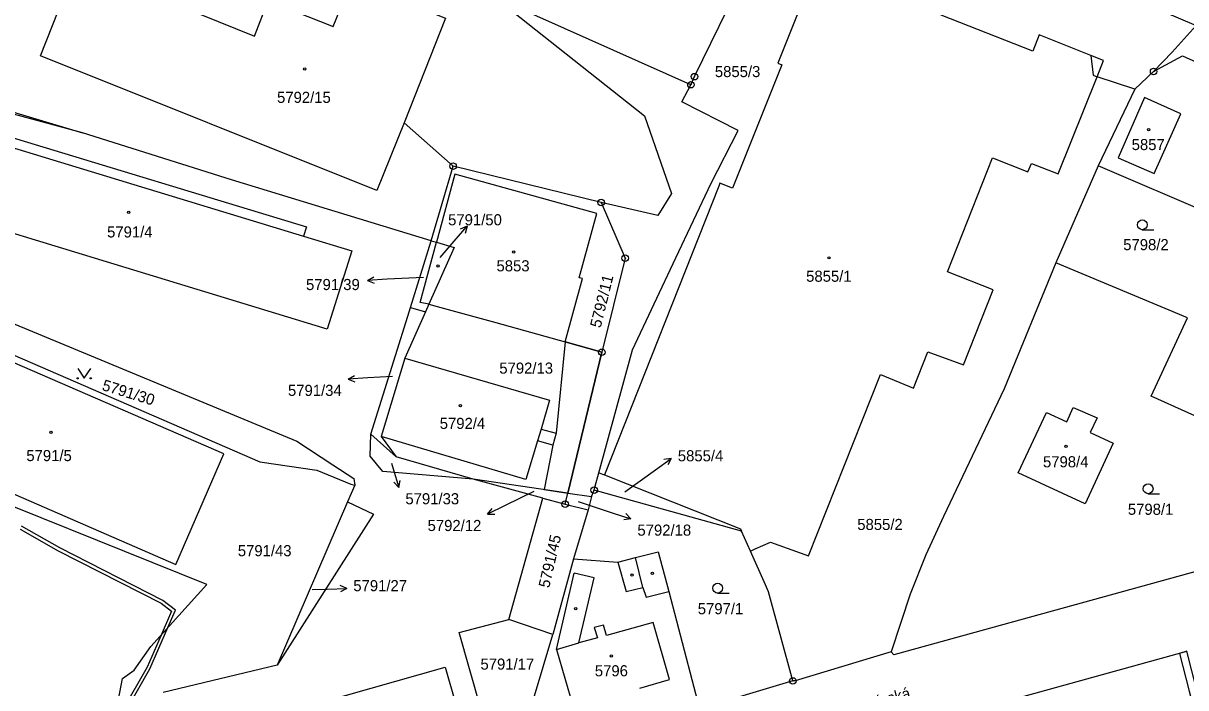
# Model space of a CAD drawing. Extents: x -644096 to -634268, y -1141430 to -1133463.
# Drawn here: x -640057.5 to -639879.7, y -1138714.8 to -1138613.2 of the extents above; entities that cross this region are included whole.
import ezdxf

# ---------------------------------------------------------------- set-up
doc = ezdxf.new("R2010")
doc.units = 0
for name, color, linetype in [('_CIVIL_CONSTRUCTION', 7, 'Continuous'), ('B_Hranice _3D', 7, 'Continuous'), ('M_Svah_Nasyp', 7, 'Continuous'), ('M_Svah_Zarez', 7, 'Continuous'), ('svrsek_osa_sjezdy', 7, 'Continuous'), ('svrsek_osa_VRT', 7, 'Continuous'), ('svrsek_popisy_VRT', 7, 'Continuous'), ('terminal_VRT', 7, 'Continuous')]:
    doc.layers.add(name, color=color, linetype=linetype)

msp = doc.modelspace()

# ---------------------------------------------------------------- linework, layer by layer
at = {"layer": '_CIVIL_CONSTRUCTION'}
for centre, radius in [((-639954.84, -1138621.41), 0.5), ((-639884.63, -1138620.63), 0.5), ((-639884.63, -1138620.63), 0.0303), ((-639955.38, -1138622.64), 0.5), ((-639955.38, -1138622.64), 0.0303), ((-639954.84, -1138621.41), 0.0303), ((-639991.77, -1138635.1), 0.5), ((-639991.77, -1138635.1), 0.0303), ((-639969.12, -1138640.64), 0.5), ((-639969.12, -1138640.64), 0.0303), ((-639965.44, -1138649.17), 0.5), ((-639965.44, -1138649.17), 0.0303), ((-639969.01, -1138663.55), 0.5), ((-639969.01, -1138663.55), 0.0303), ((-639970.2, -1138684.62), 0.5), ((-639970.2, -1138684.62), 0.0303), ((-639974.63, -1138686.76), 0.5), ((-639974.63, -1138686.76), 0.0303), ((-639939.79, -1138713.8), 0.5), ((-639939.79, -1138713.8), 0.0303)]:
    msp.add_circle(centre, radius, dxfattribs=at)
at = {"layer": 'B_Hranice _3D'}
for points in [[(-639976, -1138675.94), (-639976.53, -1138677.74), (-639977.81, -1138684.55), (-639974.22, -1138685.08), (-639969.01, -1138663.55), (-639974.63, -1138661.97)], [(-639896.28, -1138759.58), (-639894.81, -1138760.37), (-639878.16, -1138731.4), (-639875.19, -1138726.23), (-639878.01, -1138715.26), (-639879.56, -1138709.24), (-639880.69, -1138709.59), (-639879.18, -1138715.34), (-639877.32, -1138722.41), (-639876.67, -1138724.89), (-639879.22, -1138731.59)]]:
    msp.add_lwpolyline(points, close=True, dxfattribs=at)
for points in [[(-640041.9, -1138718.57), (-640038.12, -1138711.93), (-640035.37, -1138705.62), (-640034.21, -1138702.96), (-640036.15, -1138701.51), (-640051.89, -1138693.47), (-640057.74, -1138690.15)], [(-640057.98, -1138690.59), (-640052.13, -1138693.91), (-640036.41, -1138701.93), (-640034.83, -1138703.12), (-640036.42, -1138706.79), (-640038.56, -1138711.71), (-640042.38, -1138718.39)]]:
    msp.add_lwpolyline(points, dxfattribs=at)
at = {"layer": 'M_Svah_Nasyp'}
for p, q in [((-639894.25, -1138618.16), (-639893.86, -1138621.19)), ((-639893.86, -1138621.19), (-639893.29, -1138621.42)), ((-639886.01, -1138624.58), (-639890.05, -1138633.81)), ((-639880.48, -1138627.07), (-639886.01, -1138624.58)), ((-639884.56, -1138636.24), (-639880.48, -1138627.07)), ((-640060.66, -1138631.8), (-640014.64, -1138645.78)), ((-639890.05, -1138633.81), (-639884.56, -1138636.24)), ((-639978.3, -1138675.29), (-639978.85, -1138677.08)), ((-639966.55, -1138695.62), (-639965.31, -1138700.11)), ((-639962.72, -1138699.49), (-639963.88, -1138694.93)), ((-639975.93, -1138708.97), (-639973.26, -1138697.33)), ((-639970.21, -1138698.01), (-639973.26, -1138697.33)), ((-639972.52, -1138707.99), (-639970.21, -1138698.01)), ((-639965.31, -1138700.11), (-639962.72, -1138699.49)), ((-639962.72, -1138699.49), (-639962.25, -1138700.99)), ((-639962.25, -1138700.99), (-639958.78, -1138700.1)), ((-639968.74, -1138705.27), (-639970.18, -1138705.65)), ((-639970.18, -1138705.65), (-639969.67, -1138707.23)), ((-639968.3, -1138706.86), (-639968.74, -1138705.27)), ((-639961.17, -1138704.87), (-639968.3, -1138706.86)), ((-639958.67, -1138713.6), (-639961.17, -1138704.87)), ((-639975.93, -1138708.97), (-639972.52, -1138707.99)), ((-639969.67, -1138707.23), (-639972.52, -1138707.99)), ((-639975.93, -1138708.97), (-639973.41, -1138717.74)), ((-639963.19, -1138714.89), (-639958.67, -1138713.6))]:
    msp.add_line(p, q, dxfattribs=at)
at = {"layer": 'M_Svah_Zarez'}
for centre in [(-640014.44, -1138620.23), (-639885.4, -1138629.53), (-640041.36, -1138642.14), (-639982.49, -1138648.22), (-639934.29, -1138649.11), (-639994.05, -1138650.34), (-639990.64, -1138671.72), (-640053.26, -1138675.78), (-639898.03, -1138677.92), (-639964.4, -1138697.6), (-639961.28, -1138697.36), (-639973, -1138702.75), (-639967.57, -1138709.97)]:
    msp.add_circle(centre, 0.175, dxfattribs=at)
at = {"layer": 'svrsek_osa_sjezdy'}
for p, q in [((-639886.36, -1138644.81), (-639884.61, -1138644.81)), ((-639885.47, -1138685.17), (-639883.72, -1138685.17)), ((-639951.31, -1138700.36), (-639949.56, -1138700.36))]:
    msp.add_line(p, q, dxfattribs=at)
msp.add_lwpolyline([(-640049.17, -1138666.03), (-640048.17, -1138667.53), (-640047.17, -1138666.03)], dxfattribs=at)
for centre, radius in [((-639886.36, -1138644.06), 0.75), ((-640049.17, -1138667.53), 0.1), ((-640047.17, -1138667.53), 0.1), ((-639885.47, -1138684.42), 0.75), ((-639951.31, -1138699.61), 0.75)]:
    msp.add_circle(centre, radius, dxfattribs=at)
at = {"layer": 'svrsek_popisy_VRT'}
for p, q in [((-639991.59, -1138646.55), (-639989.62, -1138644.28)), ((-639989.62, -1138644.28), (-639990.66, -1138644.71)), ((-639989.62, -1138644.28), (-639989.9, -1138645.37)), ((-639993.74, -1138649.05), (-639991.59, -1138646.55)), ((-640004.85, -1138652.55), (-640003.87, -1138652)), ((-640001.85, -1138652.39), (-640004.85, -1138652.55)), ((-640004.85, -1138652.55), (-640003.82, -1138653)), ((-639996.31, -1138652.14), (-640001.85, -1138652.39)), ((-640007.82, -1138667.64), (-640006.84, -1138667.08)), ((-640001.01, -1138667.26), (-640004.82, -1138667.48)), ((-640004.82, -1138667.48), (-640007.82, -1138667.64)), ((-640007.82, -1138667.64), (-640006.79, -1138668.08)), ((-640001.19, -1138680.52), (-640000.93, -1138681.36)), ((-640000.93, -1138681.36), (-640000.05, -1138684.23)), ((-639960.83, -1138681.54), (-639958.4, -1138679.78)), ((-639958.4, -1138679.78), (-639959.51, -1138679.96)), ((-639958.4, -1138679.78), (-639958.92, -1138680.77)), ((-640000.05, -1138684.23), (-639999.87, -1138683.13)), ((-639965.52, -1138684.91), (-639960.83, -1138681.54)), ((-640000.05, -1138684.23), (-640000.82, -1138683.42)), ((-639979.4, -1138684.84), (-639983.78, -1138686.99)), ((-639972.63, -1138686.34), (-639967.42, -1138688.08)), ((-639983.78, -1138686.99), (-639986.48, -1138688.31)), ((-639986.48, -1138688.31), (-639985.8, -1138687.42)), ((-639986.48, -1138688.31), (-639985.36, -1138688.32)), ((-639967.42, -1138688.08), (-639964.57, -1138689.01)), ((-639964.57, -1138689.01), (-639965.36, -1138688.22)), ((-639964.57, -1138689.01), (-639965.67, -1138689.17)), ((-640008.02, -1138699.66), (-640009.04, -1138699.19)), ((-640013.33, -1138699.84), (-640011.02, -1138699.76)), ((-640011.02, -1138699.76), (-640008.02, -1138699.66)), ((-640008.02, -1138699.66), (-640009, -1138700.19))]:
    msp.add_line(p, q, dxfattribs=at)
at = {"layer": 'terminal_VRT'}
for p, q in [((-640048.43, -1138630.02), (-640102.51, -1138615.29)), ((-639884.63, -1138620.63), (-639887.52, -1138623.32)), ((-639887.52, -1138623.32), (-639893.29, -1138621.42)), ((-639887.52, -1138623.32), (-639893.09, -1138635.03)), ((-639991.77, -1138635.1), (-639999.22, -1138628.49)), ((-639995.09, -1138646.49), (-639991.77, -1138635.1)), ((-639969.12, -1138640.64), (-639991.77, -1138635.1)), ((-639893.09, -1138635.03), (-639899.57, -1138649.85)), ((-639872.35, -1138643.96), (-639893.09, -1138635.03)), ((-639991.47, -1138636.34), (-639994.3, -1138646.73)), ((-639998.29, -1138656.72), (-639995.09, -1138646.49)), ((-639996.8, -1138655.92), (-639994.3, -1138646.73)), ((-639995.09, -1138646.49), (-639994.3, -1138646.73)), ((-639879.45, -1138658.29), (-639899.57, -1138649.85)), ((-639995.48, -1138656.2), (-639996.8, -1138655.92)), ((-639995.48, -1138656.2), (-639996, -1138657.36)), ((-639996, -1138657.36), (-639999.15, -1138664.43)), ((-639998.29, -1138656.72), (-639996, -1138657.36)), ((-639974.63, -1138661.97), (-639969.01, -1138663.55)), ((-639969.01, -1138663.55), (-639974.22, -1138685.08)), ((-639999.15, -1138664.43), (-640002.78, -1138676.44)), ((-640000.46, -1138679.53), (-640004.32, -1138676.08)), ((-640002.78, -1138676.44), (-640000.46, -1138679.53)), ((-639988.71, -1138682.95), (-640000.46, -1138679.53)), ((-639974.22, -1138685.08), (-639988.71, -1138682.95)), ((-639978.05, -1138685.86), (-639988.71, -1138682.95)), ((-639969.46, -1138681.96), (-639968.62, -1138682.29)), ((-640006.81, -1138683.86), (-640007.91, -1138686.41)), ((-639970.58, -1138685.61), (-639970.2, -1138684.62)), ((-639947.68, -1138690.9), (-639970.2, -1138684.62)), ((-640007.91, -1138686.41), (-640018.68, -1138711.37)), ((-639983.25, -1138704.38), (-639978.05, -1138685.86)), ((-639978.05, -1138685.86), (-639974.63, -1138686.76)), ((-639974.63, -1138686.76), (-639974.22, -1138685.08)), ((-639974.63, -1138686.76), (-639971.08, -1138687.62)), ((-639974.22, -1138685.08), (-639970.58, -1138685.61)), ((-639970.58, -1138685.61), (-639971.08, -1138687.62)), ((-639971.08, -1138687.62), (-639973.33, -1138695.15)), ((-639946.29, -1138693.94), (-639947.68, -1138690.9)), ((-639973.33, -1138695.15), (-639976.51, -1138706.68)), ((-639976.51, -1138706.68), (-639983.25, -1138704.38)), ((-639904.42, -1138716.1), (-639879.56, -1138709.24)), ((-640018.68, -1138711.37), (-640036.08, -1138715.57)), ((-639939.79, -1138713.8), (-639954.1, -1138718.04))]:
    msp.add_line(p, q, dxfattribs=at)
for points in [[(-640049.33, -1138604.27), (-640047.59, -1138599.96), (-640039.49, -1138579.9), (-639988.47, -1138600.03), (-639982.8, -1138611.35), (-639962.49, -1138627.39), (-639958.38, -1138639.25), (-639960.47, -1138642.65), (-639969.12, -1138640.64)], [(-639944.38, -1138585.04), (-639918.22, -1138596.48), (-639878.15, -1138613.6), (-639881.78, -1138617.65), (-639884.63, -1138620.63)], [(-639893.29, -1138621.42), (-639892.3, -1138618.94), (-639894.25, -1138618.16), (-639902.13, -1138615.03), (-639903.11, -1138617.53), (-639917.11, -1138612), (-639916.12, -1138609.51), (-639920.83, -1138607.67), (-639922.4, -1138607.03), (-639918.59, -1138597.41), (-639941.74, -1138588.28), (-639942.43, -1138589.96), (-639944.98, -1138588.99), (-639946.77, -1138593.54), (-639944.2, -1138594.57), (-639944.9, -1138596.27), (-639934.6, -1138600.41), (-639936.18, -1138604.5)], [(-639955.38, -1138622.64), (-639982.71, -1138610.49), (-639982.16, -1138609.27), (-639977.36, -1138598.64)], [(-639999.22, -1138628.49), (-640003.44, -1138638.8), (-640054.88, -1138618.2), (-640049.33, -1138604.27)], [(-640049.33, -1138604.27), (-640030.58, -1138611.8), (-640022.13, -1138615.21), (-640020.02, -1138609.82), (-640010.12, -1138613.76), (-640007.24, -1138606.72), (-639992.92, -1138612.46), (-639999.22, -1138628.49)], [(-639936.18, -1138604.5), (-639942.08, -1138619.36), (-639941.51, -1138619.58), (-639949.03, -1138638.48), (-639950.95, -1138637.7), (-639951.13, -1138638.15), (-639968.62, -1138682.29)], [(-639955.38, -1138622.64), (-639954.84, -1138621.41), (-639946.08, -1138603.43)], [(-640098.27, -1138614.87), (-640070.74, -1138623.31), (-640048.43, -1138630.02)], [(-639884.63, -1138620.63), (-639880.24, -1138618.22), (-639863.75, -1138625.67)], [(-639969.46, -1138681.96), (-639964.3, -1138663.2), (-639957.68, -1138649.13), (-639952.27, -1138637.7), (-639948.16, -1138629.66), (-639956.76, -1138625.25), (-639955.38, -1138622.64)], [(-639946.29, -1138693.94), (-639945.57, -1138693.62), (-639943.2, -1138692.56), (-639937.39, -1138694.68), (-639926.4, -1138666.97), (-639921.37, -1138669.01), (-639919.17, -1138663.47), (-639913.73, -1138665.49), (-639909.16, -1138653.98), (-639916.13, -1138651.25), (-639909.26, -1138633.81), (-639903.85, -1138635.98), (-639903.32, -1138634.67), (-639899.24, -1138636.29), (-639893.29, -1138621.42)], [(-640007.26, -1138648.04), (-640011.01, -1138659.99), (-640071.36, -1138641.64), (-640067.6, -1138629.76), (-640060.66, -1138631.8), (-640060.19, -1138630.4), (-640014.16, -1138644.37), (-640014.64, -1138645.78), (-640007.26, -1138648.04)], [(-639995.09, -1138646.49), (-640025.67, -1138637.17), (-640048.43, -1138630.02)], [(-639974.63, -1138661.97), (-639971.99, -1138652.29), (-639972.46, -1138652.16), (-639969.78, -1138642.34), (-639991.47, -1138636.34)], [(-639969.12, -1138640.64), (-639965.44, -1138649.17), (-639969.01, -1138663.55)], [(-639994.3, -1138646.73), (-639991.62, -1138647.55), (-639995.48, -1138656.2)], [(-640093.54, -1138661.05), (-640088.72, -1138650.35), (-640087.41, -1138649.09), (-640085.43, -1138648.58), (-640083.42, -1138649.06), (-640015.66, -1138677.13), (-640010.14, -1138680.76), (-640006.92, -1138682.87), (-640006.81, -1138683.86)], [(-639899.57, -1138649.85), (-639907.48, -1138669.12), (-639916.75, -1138688.66), (-639919.45, -1138694.54), (-639921.84, -1138700.52), (-639924.75, -1138709.35)], [(-640085.47, -1138652.45), (-640071.15, -1138658.71), (-640021.31, -1138680.31), (-640012.62, -1138681.57), (-640007.39, -1138683.7), (-640006.81, -1138683.86)], [(-639995.48, -1138656.2), (-639994.18, -1138656.55), (-639985.22, -1138659), (-639974.63, -1138661.97)], [(-640004.32, -1138676.08), (-639998.69, -1138658.01), (-639998.29, -1138656.72)], [(-639868.01, -1138677.89), (-639885.02, -1138670.26), (-639879.45, -1138658.29)], [(-640034.14, -1138695.99), (-640026.82, -1138679.09), (-640071.5, -1138659.69), (-640078.82, -1138676.58), (-640034.14, -1138695.99)], [(-639999.15, -1138664.43), (-639977.01, -1138670.86), (-639978.3, -1138675.29), (-639976, -1138675.94), (-639976.53, -1138677.74), (-639978.85, -1138677.08), (-639980.63, -1138683.01), (-640002.78, -1138676.44)], [(-639893.27, -1138673.59), (-639894.31, -1138675.81), (-639890.83, -1138677.43), (-639895.12, -1138686.72), (-639905.33, -1138682), (-639901.02, -1138672.76), (-639897.92, -1138674.2), (-639896.92, -1138671.99), (-639893.27, -1138673.59)], [(-639988.71, -1138682.95), (-640002.52, -1138681.78), (-640004.43, -1138679.45), (-640004.32, -1138676.08)], [(-640047.69, -1138741.46), (-640042.29, -1138713.43), (-640040.54, -1138712.16), (-640037.98, -1138708.51), (-640029.44, -1138699.06), (-640071.54, -1138682.13)], [(-639970.2, -1138684.62), (-639970.03, -1138684.04), (-639969.46, -1138681.96)], [(-639968.62, -1138682.29), (-639947.83, -1138690.56), (-639947.68, -1138690.9)], [(-640007.91, -1138686.41), (-640003.94, -1138688.29), (-640018.68, -1138711.37)], [(-639939.79, -1138713.8), (-639943.53, -1138700.18), (-639944, -1138699.12), (-639946.29, -1138693.94)], [(-639973.33, -1138695.15), (-639966.55, -1138695.62), (-639963.88, -1138694.93), (-639960.4, -1138694.04), (-639958.78, -1138700.1), (-639954.1, -1138718.04)], [(-639875.95, -1138696.45), (-639924.37, -1138709.82), (-639924.75, -1138709.35)], [(-639990.4, -1138728.62), (-639987.55, -1138717.88), (-639990.85, -1138706.4), (-639983.25, -1138704.38)], [(-639978.08, -1138724.87), (-639979.35, -1138719.13), (-639979.33, -1138716.05), (-639976.51, -1138706.68)], [(-639924.75, -1138709.35), (-639939.45, -1138713.8), (-639939.79, -1138713.8)], [(-639992.99, -1138711.7), (-639989.81, -1138722.7), (-640031.34, -1138734.53), (-640034.45, -1138723.45), (-639992.99, -1138711.7)]]:
    msp.add_lwpolyline(points, dxfattribs=at)

# ---------------------------------------------------------------- texts
at = {"layer": 'svrsek_osa_VRT'}
for s, p in [('5855/3', (-639951.73, -1138621.48)), ('5792/15', (-640018.68, -1138625.42)), ('5857', (-639887.99, -1138632.64)), ('5791/50', (-639992.52, -1138644.14)), ('5791/4', (-640044.67, -1138646)), ('5798/2', (-639889.28, -1138647.94)), ('5853', (-639985.12, -1138651.18)), ('5855/1', (-639937.77, -1138652.77)), ('5791/39', (-640014.25, -1138654.04)), ('5792/13', (-639984.69, -1138666.82)), ('5791/34', (-640017.01, -1138670.22)), ('5792/4', (-639993.8, -1138675.27)), ('5791/5', (-640057.02, -1138680.19)), ('5855/4', (-639957.39, -1138680.22)), ('5798/4', (-639901.55, -1138681.14)), ('5791/33', (-639999.05, -1138686.79)), ('5798/1', (-639888.57, -1138688.4)), ('5792/12', (-639995.66, -1138690.88)), ('5792/18', (-639963.57, -1138691.59)), ('5855/2', (-639929.95, -1138690.72)), ('5791/43', (-640024.68, -1138694.73)), ('5791/27', (-640007.02, -1138700.08)), ('5797/1', (-639954.34, -1138703.6)), ('5791/17', (-639987.57, -1138712.07)), ('5796', (-639970.08, -1138713.09))]:
    msp.add_text(s, height=1.7, dxfattribs=at).set_placement(p)
for s, rotation, p in [('5792/11', 76, (-639969.2, -1138659.91)), ('5791/30', 343, (-640045.57, -1138669.3)), ('5791/45', 77, (-639977.07, -1138699.68))]:
    msp.add_text(s, height=1.7, rotation=rotation, dxfattribs=at).set_placement(p)
at = {"layer": 'svrsek_popisy_VRT'}
msp.add_text('Trebícská', height=1.7, rotation=15, dxfattribs=at).set_placement((-639931.32, -1138718.98))

doc.saveas('drawing.dxf')
